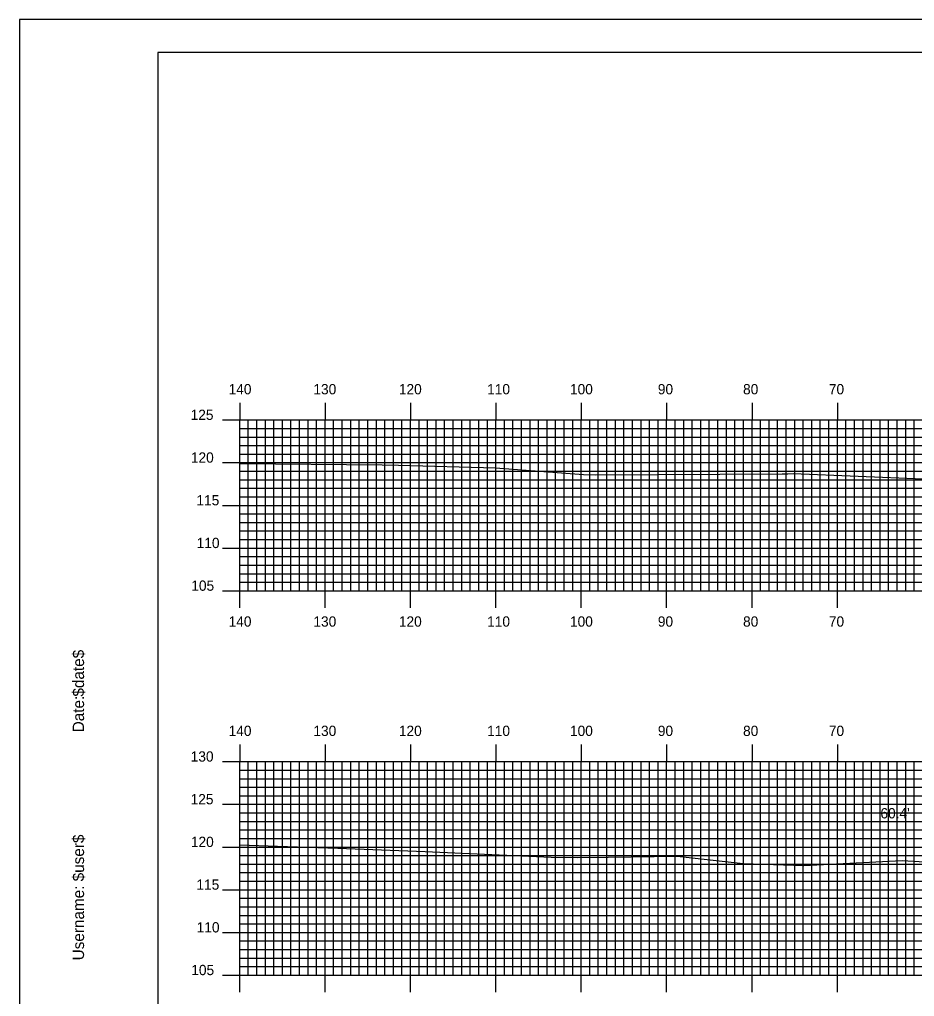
# Model space of a CAD drawing. Extents: x 1780286 to 1780629, y 442591 to 442811.
# Drawn here: x 1780286.1 to 1780390.9, y 442696.2 to 442810.5 of the extents above; entities that cross this region are included whole.
import ezdxf

# ---------------------------------------------------------------- set-up
doc = ezdxf.new("R2010")
doc.units = 0
for name, color, linetype in [('BORDER', 7, 'Continuous'), ('D_Text_Standard', 7, 'Continuous'), ('H_V ANNOTATION', 7, 'Continuous'), ('MAJOR', 7, 'Continuous'), ('MINOR', 7, 'Continuous'), ('PLOT BOUNDARY', 7, 'Continuous'), ('S_Roadway_Centerline', 7, 'Continuous')]:
    doc.layers.add(name, color=color, linetype=linetype)

msp = doc.modelspace()

# ---------------------------------------------------------------- linework, layer by layer
at = {"layer": 'BORDER'}
msp.add_lwpolyline([(1780302.27, 442596.67), (1780622.27, 442596.67), (1780622.27, 442806.67), (1780302.27, 442806.67)], close=True, dxfattribs=at)
at = {"layer": 'MAJOR'}
for p, q in [((1780311.87, 442765.67), (1780311.87, 442763.67)), ((1780321.87, 442765.67), (1780321.87, 442763.67)), ((1780331.87, 442765.67), (1780331.87, 442763.67)), ((1780341.87, 442765.67), (1780341.87, 442763.67)), ((1780351.87, 442765.67), (1780351.87, 442763.67)), ((1780361.87, 442765.67), (1780361.87, 442763.67)), ((1780371.87, 442765.67), (1780371.87, 442763.67)), ((1780381.87, 442765.67), (1780381.87, 442763.67)), ((1780309.86, 442763.67), (1780311.87, 442763.67)), ((1780311.87, 442763.67), (1780591.87, 442763.67)), ((1780311.87, 442743.67), (1780311.87, 442763.67)), ((1780311.87, 442743.67), (1780311.87, 442763.67)), ((1780311.87, 442763.67), (1780591.87, 442763.67)), ((1780321.87, 442743.67), (1780321.87, 442763.67)), ((1780331.87, 442743.67), (1780331.87, 442763.67)), ((1780341.87, 442743.67), (1780341.87, 442763.67)), ((1780351.87, 442743.67), (1780351.87, 442763.67)), ((1780361.87, 442743.67), (1780361.87, 442763.67)), ((1780371.87, 442743.67), (1780371.87, 442763.67)), ((1780381.87, 442743.67), (1780381.87, 442763.67)), ((1780309.86, 442758.67), (1780311.87, 442758.67)), ((1780311.87, 442758.67), (1780591.87, 442758.67)), ((1780309.86, 442753.67), (1780311.87, 442753.67)), ((1780311.87, 442753.67), (1780591.87, 442753.67)), ((1780309.86, 442748.67), (1780311.87, 442748.67)), ((1780311.87, 442748.67), (1780591.87, 442748.67)), ((1780309.86, 442743.67), (1780311.87, 442743.67)), ((1780311.87, 442743.67), (1780591.87, 442743.67)), ((1780311.87, 442743.67), (1780591.87, 442743.67)), ((1780311.87, 442741.66), (1780311.87, 442743.67)), ((1780321.87, 442741.66), (1780321.87, 442743.67)), ((1780331.87, 442741.66), (1780331.87, 442743.67)), ((1780341.87, 442741.66), (1780341.87, 442743.67)), ((1780351.87, 442741.66), (1780351.87, 442743.67)), ((1780361.87, 442741.66), (1780361.87, 442743.67)), ((1780371.87, 442741.66), (1780371.87, 442743.67)), ((1780381.87, 442741.66), (1780381.87, 442743.67)), ((1780311.87, 442725.67), (1780311.87, 442723.67)), ((1780321.87, 442725.67), (1780321.87, 442723.67)), ((1780331.87, 442725.67), (1780331.87, 442723.67)), ((1780341.87, 442725.67), (1780341.87, 442723.67)), ((1780351.87, 442725.67), (1780351.87, 442723.67)), ((1780361.87, 442725.67), (1780361.87, 442723.67)), ((1780371.87, 442725.67), (1780371.87, 442723.67)), ((1780381.87, 442725.67), (1780381.87, 442723.67)), ((1780309.86, 442723.67), (1780311.87, 442723.67)), ((1780311.87, 442723.67), (1780591.87, 442723.67)), ((1780311.87, 442698.67), (1780311.87, 442723.67)), ((1780311.87, 442698.67), (1780311.87, 442723.67)), ((1780311.87, 442723.67), (1780591.87, 442723.67)), ((1780321.87, 442698.67), (1780321.87, 442723.67)), ((1780331.87, 442698.67), (1780331.87, 442723.67)), ((1780341.87, 442698.67), (1780341.87, 442723.67)), ((1780351.87, 442698.67), (1780351.87, 442723.67)), ((1780361.87, 442698.67), (1780361.87, 442723.67)), ((1780371.87, 442698.67), (1780371.87, 442723.67)), ((1780381.87, 442698.67), (1780381.87, 442723.67)), ((1780309.86, 442718.67), (1780311.87, 442718.67)), ((1780311.87, 442718.67), (1780591.87, 442718.67)), ((1780309.86, 442713.67), (1780311.87, 442713.67)), ((1780311.87, 442713.67), (1780591.87, 442713.67)), ((1780309.86, 442708.67), (1780311.87, 442708.67)), ((1780311.87, 442708.67), (1780591.87, 442708.67)), ((1780309.86, 442703.67), (1780311.87, 442703.67)), ((1780311.87, 442703.67), (1780591.87, 442703.67)), ((1780309.86, 442698.67), (1780311.87, 442698.67)), ((1780311.87, 442698.67), (1780591.87, 442698.67)), ((1780311.87, 442698.67), (1780591.87, 442698.67)), ((1780311.87, 442696.66), (1780311.87, 442698.67)), ((1780321.87, 442696.66), (1780321.87, 442698.67)), ((1780331.87, 442696.66), (1780331.87, 442698.67)), ((1780341.87, 442696.66), (1780341.87, 442698.67)), ((1780351.87, 442696.66), (1780351.87, 442698.67)), ((1780361.87, 442696.66), (1780361.87, 442698.67)), ((1780371.87, 442696.66), (1780371.87, 442698.67)), ((1780381.87, 442696.66), (1780381.87, 442698.67))]:
    msp.add_line(p, q, dxfattribs=at)
at = {"layer": 'MINOR'}
for p, q in [((1780312.87, 442743.67), (1780312.87, 442763.67)), ((1780313.87, 442743.67), (1780313.87, 442763.67)), ((1780314.87, 442743.67), (1780314.87, 442763.67)), ((1780315.87, 442743.67), (1780315.87, 442763.67)), ((1780316.87, 442743.67), (1780316.87, 442763.67)), ((1780317.87, 442743.67), (1780317.87, 442763.67)), ((1780318.87, 442743.67), (1780318.87, 442763.67)), ((1780319.87, 442743.67), (1780319.87, 442763.67)), ((1780320.87, 442743.67), (1780320.87, 442763.67)), ((1780322.87, 442743.67), (1780322.87, 442763.67)), ((1780323.87, 442743.67), (1780323.87, 442763.67)), ((1780324.87, 442743.67), (1780324.87, 442763.67)), ((1780325.87, 442743.67), (1780325.87, 442763.67)), ((1780326.87, 442743.67), (1780326.87, 442763.67)), ((1780327.87, 442743.67), (1780327.87, 442763.67)), ((1780328.87, 442743.67), (1780328.87, 442763.67)), ((1780329.87, 442743.67), (1780329.87, 442763.67)), ((1780330.87, 442743.67), (1780330.87, 442763.67)), ((1780332.87, 442743.67), (1780332.87, 442763.67)), ((1780333.87, 442743.67), (1780333.87, 442763.67)), ((1780334.87, 442743.67), (1780334.87, 442763.67)), ((1780335.87, 442743.67), (1780335.87, 442763.67)), ((1780336.87, 442743.67), (1780336.87, 442763.67)), ((1780337.87, 442743.67), (1780337.87, 442763.67)), ((1780338.87, 442743.67), (1780338.87, 442763.67)), ((1780339.87, 442743.67), (1780339.87, 442763.67)), ((1780340.87, 442743.67), (1780340.87, 442763.67)), ((1780342.87, 442743.67), (1780342.87, 442763.67)), ((1780343.87, 442743.67), (1780343.87, 442763.67)), ((1780344.87, 442743.67), (1780344.87, 442763.67)), ((1780345.87, 442743.67), (1780345.87, 442763.67)), ((1780346.87, 442743.67), (1780346.87, 442763.67)), ((1780347.87, 442743.67), (1780347.87, 442763.67)), ((1780348.87, 442743.67), (1780348.87, 442763.67)), ((1780349.87, 442743.67), (1780349.87, 442763.67)), ((1780350.87, 442743.67), (1780350.87, 442763.67)), ((1780352.87, 442743.67), (1780352.87, 442763.67)), ((1780353.87, 442743.67), (1780353.87, 442763.67)), ((1780354.87, 442743.67), (1780354.87, 442763.67)), ((1780355.87, 442743.67), (1780355.87, 442763.67)), ((1780356.87, 442743.67), (1780356.87, 442763.67)), ((1780357.87, 442743.67), (1780357.87, 442763.67)), ((1780358.87, 442743.67), (1780358.87, 442763.67)), ((1780359.87, 442743.67), (1780359.87, 442763.67)), ((1780360.87, 442743.67), (1780360.87, 442763.67)), ((1780362.87, 442743.67), (1780362.87, 442763.67)), ((1780363.87, 442743.67), (1780363.87, 442763.67)), ((1780364.87, 442743.67), (1780364.87, 442763.67)), ((1780365.87, 442743.67), (1780365.87, 442763.67)), ((1780366.87, 442743.67), (1780366.87, 442763.67)), ((1780367.87, 442743.67), (1780367.87, 442763.67)), ((1780368.87, 442743.67), (1780368.87, 442763.67)), ((1780369.87, 442743.67), (1780369.87, 442763.67)), ((1780370.87, 442743.67), (1780370.87, 442763.67)), ((1780372.87, 442743.67), (1780372.87, 442763.67)), ((1780373.87, 442743.67), (1780373.87, 442763.67)), ((1780374.87, 442743.67), (1780374.87, 442763.67)), ((1780375.87, 442743.67), (1780375.87, 442763.67)), ((1780376.87, 442743.67), (1780376.87, 442763.67)), ((1780377.87, 442743.67), (1780377.87, 442763.67)), ((1780378.87, 442743.67), (1780378.87, 442763.67)), ((1780379.87, 442743.67), (1780379.87, 442763.67)), ((1780380.87, 442743.67), (1780380.87, 442763.67)), ((1780382.87, 442743.67), (1780382.87, 442763.67)), ((1780383.87, 442743.67), (1780383.87, 442763.67)), ((1780384.87, 442743.67), (1780384.87, 442763.67)), ((1780385.87, 442743.67), (1780385.87, 442763.67)), ((1780386.87, 442743.67), (1780386.87, 442763.67)), ((1780387.87, 442743.67), (1780387.87, 442763.67)), ((1780388.87, 442743.67), (1780388.87, 442763.67)), ((1780389.87, 442743.67), (1780389.87, 442763.67)), ((1780390.87, 442743.67), (1780390.87, 442763.67)), ((1780311.87, 442762.67), (1780591.87, 442762.67)), ((1780311.87, 442762.67), (1780313.87, 442762.67)), ((1780311.87, 442761.67), (1780591.87, 442761.67)), ((1780311.87, 442761.67), (1780313.87, 442761.67)), ((1780311.87, 442760.67), (1780591.87, 442760.67)), ((1780311.87, 442760.67), (1780313.87, 442760.67)), ((1780311.87, 442759.67), (1780591.87, 442759.67)), ((1780311.87, 442759.67), (1780313.87, 442759.67)), ((1780311.87, 442757.67), (1780591.87, 442757.67)), ((1780311.87, 442757.67), (1780313.87, 442757.67)), ((1780311.87, 442756.67), (1780591.87, 442756.67)), ((1780311.87, 442756.67), (1780313.87, 442756.67)), ((1780311.87, 442755.67), (1780591.87, 442755.67)), ((1780311.87, 442755.67), (1780313.87, 442755.67)), ((1780311.87, 442754.67), (1780591.87, 442754.67)), ((1780311.87, 442754.67), (1780313.87, 442754.67)), ((1780311.87, 442752.67), (1780591.87, 442752.67)), ((1780311.87, 442752.67), (1780313.87, 442752.67)), ((1780311.87, 442751.67), (1780591.87, 442751.67)), ((1780311.87, 442751.67), (1780313.87, 442751.67)), ((1780311.87, 442750.67), (1780591.87, 442750.67)), ((1780311.87, 442750.67), (1780313.87, 442750.67)), ((1780311.87, 442749.67), (1780591.87, 442749.67)), ((1780311.87, 442749.67), (1780313.87, 442749.67)), ((1780311.87, 442747.67), (1780591.87, 442747.67)), ((1780311.87, 442747.67), (1780313.87, 442747.67)), ((1780311.87, 442746.67), (1780591.87, 442746.67)), ((1780311.87, 442746.67), (1780313.87, 442746.67)), ((1780311.87, 442745.67), (1780591.87, 442745.67)), ((1780311.87, 442745.67), (1780313.87, 442745.67)), ((1780311.87, 442744.67), (1780591.87, 442744.67)), ((1780311.87, 442744.67), (1780313.87, 442744.67)), ((1780312.87, 442698.67), (1780312.87, 442723.67)), ((1780313.87, 442698.67), (1780313.87, 442723.67)), ((1780314.87, 442698.67), (1780314.87, 442723.67)), ((1780315.87, 442698.67), (1780315.87, 442723.67)), ((1780316.87, 442698.67), (1780316.87, 442723.67)), ((1780317.87, 442698.67), (1780317.87, 442723.67)), ((1780318.87, 442698.67), (1780318.87, 442723.67)), ((1780319.87, 442698.67), (1780319.87, 442723.67)), ((1780320.87, 442698.67), (1780320.87, 442723.67)), ((1780322.87, 442698.67), (1780322.87, 442723.67)), ((1780323.87, 442698.67), (1780323.87, 442723.67)), ((1780324.87, 442698.67), (1780324.87, 442723.67)), ((1780325.87, 442698.67), (1780325.87, 442723.67)), ((1780326.87, 442698.67), (1780326.87, 442723.67)), ((1780327.87, 442698.67), (1780327.87, 442723.67)), ((1780328.87, 442698.67), (1780328.87, 442723.67)), ((1780329.87, 442698.67), (1780329.87, 442723.67)), ((1780330.87, 442698.67), (1780330.87, 442723.67)), ((1780332.87, 442698.67), (1780332.87, 442723.67)), ((1780333.87, 442698.67), (1780333.87, 442723.67)), ((1780334.87, 442698.67), (1780334.87, 442723.67)), ((1780335.87, 442698.67), (1780335.87, 442723.67)), ((1780336.87, 442698.67), (1780336.87, 442723.67)), ((1780337.87, 442698.67), (1780337.87, 442723.67)), ((1780338.87, 442698.67), (1780338.87, 442723.67)), ((1780339.87, 442698.67), (1780339.87, 442723.67)), ((1780340.87, 442698.67), (1780340.87, 442723.67)), ((1780342.87, 442698.67), (1780342.87, 442723.67)), ((1780343.87, 442698.67), (1780343.87, 442723.67)), ((1780344.87, 442698.67), (1780344.87, 442723.67)), ((1780345.87, 442698.67), (1780345.87, 442723.67)), ((1780346.87, 442698.67), (1780346.87, 442723.67)), ((1780347.87, 442698.67), (1780347.87, 442723.67)), ((1780348.87, 442698.67), (1780348.87, 442723.67)), ((1780349.87, 442698.67), (1780349.87, 442723.67)), ((1780350.87, 442698.67), (1780350.87, 442723.67)), ((1780352.87, 442698.67), (1780352.87, 442723.67)), ((1780353.87, 442698.67), (1780353.87, 442723.67)), ((1780354.87, 442698.67), (1780354.87, 442723.67)), ((1780355.87, 442698.67), (1780355.87, 442723.67)), ((1780356.87, 442698.67), (1780356.87, 442723.67)), ((1780357.87, 442698.67), (1780357.87, 442723.67)), ((1780358.87, 442698.67), (1780358.87, 442723.67)), ((1780359.87, 442698.67), (1780359.87, 442723.67)), ((1780360.87, 442698.67), (1780360.87, 442723.67)), ((1780362.87, 442698.67), (1780362.87, 442723.67)), ((1780363.87, 442698.67), (1780363.87, 442723.67)), ((1780364.87, 442698.67), (1780364.87, 442723.67)), ((1780365.87, 442698.67), (1780365.87, 442723.67)), ((1780366.87, 442698.67), (1780366.87, 442723.67)), ((1780367.87, 442698.67), (1780367.87, 442723.67)), ((1780368.87, 442698.67), (1780368.87, 442723.67)), ((1780369.87, 442698.67), (1780369.87, 442723.67)), ((1780370.87, 442698.67), (1780370.87, 442723.67)), ((1780372.87, 442698.67), (1780372.87, 442723.67)), ((1780373.87, 442698.67), (1780373.87, 442723.67)), ((1780374.87, 442698.67), (1780374.87, 442723.67)), ((1780375.87, 442698.67), (1780375.87, 442723.67)), ((1780376.87, 442698.67), (1780376.87, 442723.67)), ((1780377.87, 442698.67), (1780377.87, 442723.67)), ((1780378.87, 442698.67), (1780378.87, 442723.67)), ((1780379.87, 442698.67), (1780379.87, 442723.67)), ((1780380.87, 442698.67), (1780380.87, 442723.67)), ((1780382.87, 442698.67), (1780382.87, 442723.67)), ((1780383.87, 442698.67), (1780383.87, 442723.67)), ((1780384.87, 442698.67), (1780384.87, 442723.67)), ((1780385.87, 442698.67), (1780385.87, 442723.67)), ((1780386.87, 442698.67), (1780386.87, 442723.67)), ((1780387.87, 442698.67), (1780387.87, 442723.67)), ((1780388.87, 442698.67), (1780388.87, 442723.67)), ((1780389.87, 442698.67), (1780389.87, 442723.67)), ((1780390.87, 442698.67), (1780390.87, 442723.67)), ((1780311.87, 442722.67), (1780591.87, 442722.67)), ((1780311.87, 442722.67), (1780313.87, 442722.67)), ((1780311.87, 442721.67), (1780591.87, 442721.67)), ((1780311.87, 442721.67), (1780313.87, 442721.67)), ((1780311.87, 442720.67), (1780591.87, 442720.67)), ((1780311.87, 442720.67), (1780313.87, 442720.67)), ((1780311.87, 442719.67), (1780591.87, 442719.67)), ((1780311.87, 442719.67), (1780313.87, 442719.67)), ((1780311.87, 442717.67), (1780591.87, 442717.67)), ((1780311.87, 442717.67), (1780313.87, 442717.67)), ((1780311.87, 442716.67), (1780591.87, 442716.67)), ((1780311.87, 442716.67), (1780313.87, 442716.67)), ((1780311.87, 442715.67), (1780591.87, 442715.67)), ((1780311.87, 442715.67), (1780313.87, 442715.67)), ((1780311.87, 442714.67), (1780591.87, 442714.67)), ((1780311.87, 442714.67), (1780313.87, 442714.67)), ((1780311.87, 442712.67), (1780591.87, 442712.67)), ((1780311.87, 442712.67), (1780313.87, 442712.67)), ((1780311.87, 442711.67), (1780591.87, 442711.67)), ((1780311.87, 442711.67), (1780313.87, 442711.67)), ((1780311.87, 442710.67), (1780591.87, 442710.67)), ((1780311.87, 442710.67), (1780313.87, 442710.67)), ((1780311.87, 442709.67), (1780591.87, 442709.67)), ((1780311.87, 442709.67), (1780313.87, 442709.67)), ((1780311.87, 442707.67), (1780591.87, 442707.67)), ((1780311.87, 442707.67), (1780313.87, 442707.67)), ((1780311.87, 442706.67), (1780591.87, 442706.67)), ((1780311.87, 442706.67), (1780313.87, 442706.67)), ((1780311.87, 442705.67), (1780591.87, 442705.67)), ((1780311.87, 442705.67), (1780313.87, 442705.67)), ((1780311.87, 442704.67), (1780591.87, 442704.67)), ((1780311.87, 442704.67), (1780313.87, 442704.67)), ((1780311.87, 442702.67), (1780591.87, 442702.67)), ((1780311.87, 442702.67), (1780313.87, 442702.67)), ((1780311.87, 442701.67), (1780591.87, 442701.67)), ((1780311.87, 442701.67), (1780313.87, 442701.67)), ((1780311.87, 442700.67), (1780591.87, 442700.67)), ((1780311.87, 442700.67), (1780313.87, 442700.67)), ((1780311.87, 442699.67), (1780591.87, 442699.67)), ((1780311.87, 442699.67), (1780313.87, 442699.67))]:
    msp.add_line(p, q, dxfattribs=at)
at = {"layer": 'PLOT BOUNDARY'}
msp.add_lwpolyline([(1780286.08, 442590.55), (1780626.08, 442590.55), (1780626.08, 442810.55), (1780286.08, 442810.55)], close=True, dxfattribs=at)
at = {"layer": 'S_Roadway_Centerline'}
for points in [[(1780311.87, 442758.55), (1780328.56, 442758.42), (1780330.47, 442758.37), (1780341.82, 442758.06), (1780352.12, 442757.29), (1780353.5, 442757.25), (1780375.41, 442757.37), (1780376.06, 442757.36), (1780376.68, 442757.38), (1780399.51, 442756.46), (1780400.54, 442756.42), (1780402.33, 442756.33), (1780421.57, 442755.84), (1780434.05, 442755.5), (1780441.33, 442756.1), (1780453.75, 442755.7), (1780461.38, 442755.33), (1780463.3, 442755.31), (1780473.35, 442754.45), (1780486.1, 442754.17), (1780495.91, 442753.89), (1780507.1, 442753.7)], [(1780311.87, 442713.92), (1780316.28, 442713.77), (1780323.35, 442713.53), (1780333.58, 442713.13), (1780348.35, 442712.48), (1780351.46, 442712.45), (1780355.02, 442712.48), (1780363.09, 442712.6), (1780370.85, 442711.72), (1780377.94, 442711.49), (1780389.46, 442712.1), (1780394.76, 442711.79)]]:
    msp.add_lwpolyline(points, dxfattribs=at)

# ---------------------------------------------------------------- texts
at = {"layer": 'BORDER'}
for s, p in [('$date$', (1780293.64, 442731.28)), ('Date:', (1780293.64, 442727.1)), ('$user$', (1780293.64, 442709.65)), ('Username:', (1780293.64, 442700.4))]:
    msp.add_text(s, height=1.339, rotation=90, dxfattribs=at).set_placement(p)
at = {"layer": 'D_Text_Standard'}
msp.add_text("60.4'", height=1.2, dxfattribs=at).set_placement((1780386.91, 442717.02))
at = {"layer": 'H_V ANNOTATION'}
for s, p in [('140', (1780310.57, 442766.67)), ('130', (1780320.5, 442766.67)), ('120', (1780330.51, 442766.67)), ('110', (1780340.85, 442766.67)), ('100', (1780350.55, 442766.67)), ('90', (1780360.84, 442766.67)), ('80', (1780370.82, 442766.67)), ('70', (1780380.87, 442766.67)), ('125', (1780306.12, 442763.67)), ('120', (1780306.15, 442758.67)), ('115', (1780306.8, 442753.67)), ('110', (1780306.83, 442748.67)), ('105', (1780306.2, 442743.67)), ('140', (1780310.57, 442739.47)), ('130', (1780320.5, 442739.47)), ('120', (1780330.51, 442739.47)), ('110', (1780340.85, 442739.47)), ('100', (1780350.55, 442739.47)), ('90', (1780360.84, 442739.47)), ('80', (1780370.82, 442739.47)), ('70', (1780380.87, 442739.47)), ('140', (1780310.57, 442726.67)), ('130', (1780320.5, 442726.67)), ('120', (1780330.51, 442726.67)), ('110', (1780340.85, 442726.67)), ('100', (1780350.55, 442726.67)), ('90', (1780360.84, 442726.67)), ('80', (1780370.82, 442726.67)), ('70', (1780380.87, 442726.67)), ('130', (1780306.13, 442723.67)), ('125', (1780306.12, 442718.67)), ('120', (1780306.15, 442713.67)), ('115', (1780306.8, 442708.67)), ('110', (1780306.83, 442703.67)), ('105', (1780306.2, 442698.67))]:
    msp.add_text(s, height=1.2, dxfattribs=at).set_placement(p)
at = {"layer": 'MAJOR'}
for p in [(1780311.86, 442743.67), (1780311.86, 442698.67)]:
    msp.add_text('-', height=0.012, dxfattribs=at).set_placement(p)

doc.saveas('drawing.dxf')
